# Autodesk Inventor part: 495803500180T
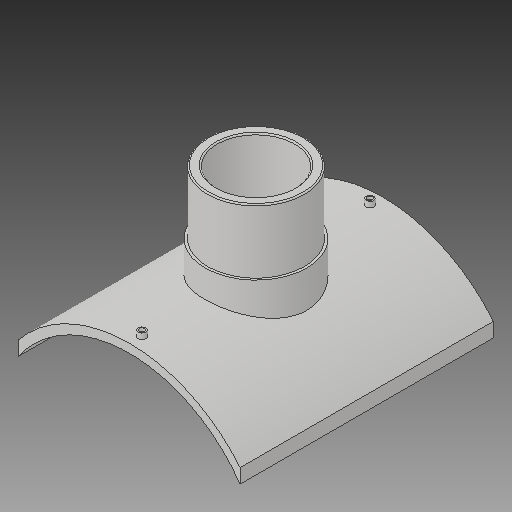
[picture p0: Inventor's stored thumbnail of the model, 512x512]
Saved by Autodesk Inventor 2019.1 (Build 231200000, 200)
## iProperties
Created: 2017-10
Part Number: 495803500180T
Material: Generic
Description: PLASSON BRANCH SADDLE  500x180
Document SubType Name: Modeling
Designer: KIM
Mass: 2754.05 g
Surface Area: 3037.44 cm^2
Volume: 2754.05 cm^3
Density: 1 g/cm^3
Appearance: Default
Author: KIM
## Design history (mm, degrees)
derived "495803.ipt"
feature "Solid1::495803.ipt"
tag "TaggingFeature1"
body "Solid1"
other parameters: "d1" = 16, "d2" = 411, "d4" = 0, "d12" = 275.6, "d13" = 14, "d14" = 211.5, "d16" = 5 deg, "d18" = 4, "d19" = 14, "d20" = 0, "d21" = 3, "d22" = 0, "d23" = 435, "d24" = 189, "d25" = 16, "d26" = 144, "d28" = 0, "d29" = 9.6, "d31" = 0, "d32" = 84.5, "d33" = 0, "d34" = 5, "d37" = 118.3, "d38" = 0, "d39" = 2.5, "B_" = 411, "H_" = 169, "x_" = 16, "D_" = 16
